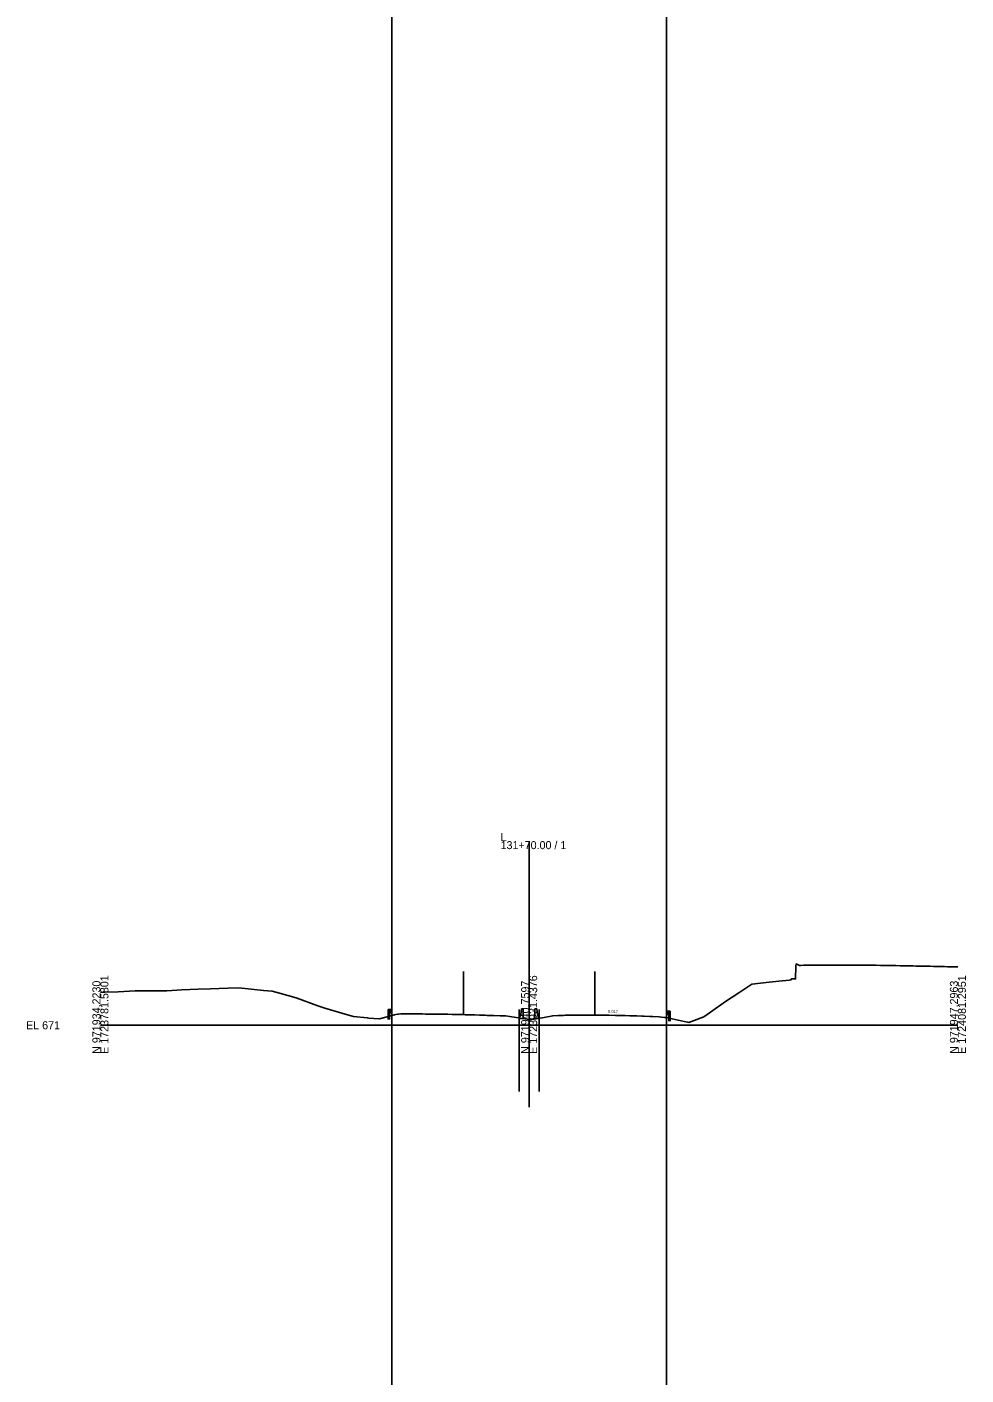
# Model space of a CAD drawing. Extents: x -26 to 303, y -29 to 15026.
# Drawn here: x -25.7 to 302.8, y 6377.7 to 6849.2 of the extents above; entities that cross this region are included whole.
import ezdxf

# ---------------------------------------------------------------- set-up
doc = ezdxf.new("R2010")
doc.units = 0
for name, color, linetype in [('Exist Cross Section Cell', 7, 'Continuous'), ('Exist XS Center Line Elevation Label', 7, 'Continuous'), ('Exist XS Ground Line', 7, 'Continuous'), ('Prop XS Ditch Standard Text', 7, 'Continuous'), ('Scratch_Level_0', 7, 'Continuous'), ('Typical Guardrail CELL', 7, 'Continuous'), ('Typical Median Barrier CELL', 7, 'Continuous')]:
    doc.layers.add(name, color=color, linetype=linetype)

msp = doc.modelspace()

# ---------------------------------------------------------------- linework, layer by layer
at = {"layer": 'Exist Cross Section Cell'}
for p, q in [((150, 6500), (150, 6564.41)), ((0, 6500), (150, 6500)), ((150, 6500), (300, 6500))]:
    msp.add_line(p, q, dxfattribs=at)
at = {"layer": 'Exist XS Ground Line'}
msp.add_lwpolyline([(0, 6511.5), (1.51, 6511.56), (6.17, 6511.73), (12.12, 6512.05), (18.24, 6512.02), (23.22, 6512.05), (28.46, 6512.36), (34.18, 6512.63), (38.47, 6512.75), (44.64, 6512.95), (48.48, 6513.12), (57.08, 6512.2), (60.09, 6511.97), (62.7, 6511.22), (68.49, 6509.6), (76.04, 6506.78), (78.5, 6505.99), (86.5, 6503.67), (88.51, 6503.12), (93.37, 6502.62), (93.94, 6502.48), (95.62, 6502.37), (97.68, 6502.21), (98.14, 6502.33), (102.9, 6503.63), (103.37, 6503.81), (103.91, 6503.88), (104.3, 6503.94), (105.15, 6503.98), (105.86, 6503.98), (107.61, 6503.99), (109.27, 6503.97), (110.13, 6503.97), (110.91, 6503.97), (111.29, 6503.97), (111.82, 6503.96), (112.64, 6503.95), (113.68, 6503.94), (115.14, 6503.92), (116.47, 6503.91), (117.64, 6503.9), (118.88, 6503.87), (120.13, 6503.85), (121.49, 6503.83), (123.06, 6503.81), (124.03, 6503.78), (125.11, 6503.76), (126.72, 6503.71), (127.62, 6503.69), (129.36, 6503.64), (130.14, 6503.62), (130.84, 6503.6), (132.62, 6503.56), (134.6, 6503.5), (135.32, 6503.47), (135.73, 6503.46), (137.2, 6503.42), (137.64, 6503.41), (139.81, 6503.35), (140.27, 6503.33), (141.77, 6503.29), (143.19, 6503.02), (150, 6502), (150.35, 6501.95), (155.21, 6502.72), (158.27, 6503.35), (160.13, 6503.4), (161.99, 6503.46), (162.65, 6503.49), (163.45, 6503.51), (164.44, 6503.53), (164.77, 6503.53), (165.16, 6503.53), (166.8, 6503.53), (167.67, 6503.53), (168.61, 6503.54), (170.2, 6503.55), (171.63, 6503.54), (172.69, 6503.53), (174.04, 6503.53), (175.2, 6503.53), (176.83, 6503.51), (177.25, 6503.51), (177.98, 6503.49), (180.18, 6503.44), (181.67, 6503.4), (182.67, 6503.38), (183.58, 6503.36), (185.18, 6503.31), (186.92, 6503.27), (187.67, 6503.25), (189.43, 6503.2), (190.2, 6503.16), (192.17, 6503.08), (192.67, 6503.06), (193.14, 6503.04), (195.5, 6502.91), (196.31, 6502.87), (197.33, 6502.74), (197.92, 6502.66), (199.05, 6502.53), (200.06, 6502.24), (204.21, 6501.36), (205.49, 6501.04), (205.84, 6501.02), (206.77, 6501.37), (211.14, 6502.97), (213.44, 6504.59), (218.63, 6508.35), (223.35, 6511.35), (227.88, 6514.34), (233.96, 6515.02), (238.54, 6515.57), (241.05, 6515.82), (241.65, 6515.95), (241.75, 6516.23), (242.3, 6516.23), (243.21, 6516.22), (243.31, 6520.72), (243.46, 6521.47), (244.58, 6520.93), (245.03, 6520.96), (245.94, 6520.99), (246.38, 6521), (246.98, 6521.01), (247.68, 6521.03), (250.01, 6521.05), (251.25, 6521.05), (252.63, 6521.04), (255.03, 6521.04), (257.75, 6521.05), (260.04, 6521.04), (260.45, 6521.04), (262.54, 6521.02), (264.48, 6521.02), (265.04, 6521.01), (266.88, 6521), (267.53, 6521), (268.24, 6520.99), (269.43, 6520.98), (271.37, 6520.97), (272.9, 6520.95), (273.95, 6520.93), (274.77, 6520.92), (276.6, 6520.89), (278.27, 6520.87), (279.75, 6520.83), (280.58, 6520.82), (282.34, 6520.78), (282.78, 6520.77), (284.33, 6520.74), (285.29, 6520.72), (286.33, 6520.7), (287.78, 6520.67), (288.94, 6520.65), (290.27, 6520.62), (291.51, 6520.59), (292.78, 6520.57), (293.91, 6520.54), (295.29, 6520.51), (296.32, 6520.48), (297.79, 6520.44), (298.73, 6520.42), (300, 6520.39)], dxfattribs=at)
at = {"layer": 'Scratch_Level_0'}
for p, q in [((102, 15009.56), (102, -28.7)), ((198, 15009.56), (198, -28.7)), ((127, 6518.8), (127, 6503.71)), ((173, 6518.8), (173, 6503.53)), ((146.46, 6505.5), (146.46, 6476.8)), ((153.54, 6505.5), (153.54, 6476.8)), ((173, 6503.53), (183.58, 6503.36)), ((150, 6500), (150, 6471.3)), ((150, 6500), (150, 6471.3))]:
    msp.add_line(p, q, dxfattribs=at)
at = {"layer": 'Typical Guardrail CELL'}
for p, q in [((101.18, 6505.51), (100.68, 6505.51)), ((100.68, 6505.51), (100.68, 6503.02)), ((101.18, 6503.02), (100.68, 6503.02)), ((100.68, 6503.02), (100.68, 6502.01)), ((101.18, 6505.51), (101.18, 6503.02)), ((101.18, 6505.51), (101.68, 6505.51)), ((101.18, 6504.35), (101.68, 6504.35)), ((101.18, 6503.02), (101.18, 6502.01)), ((101.68, 6505.51), (101.68, 6504.35)), ((101.68, 6505.51), (101.97, 6505.31)), ((101.68, 6504.98), (101.97, 6505.18)), ((101.68, 6504.93), (101.68, 6504.98)), ((101.68, 6504.93), (101.68, 6504.88)), ((101.68, 6504.88), (101.97, 6504.68)), ((101.68, 6504.35), (101.97, 6504.55)), ((198.32, 6504.94), (198.03, 6504.74)), ((198.32, 6504.41), (198.03, 6504.61)), ((198.32, 6504.31), (198.03, 6504.11)), ((198.32, 6503.78), (198.03, 6503.98)), ((198.82, 6504.94), (198.32, 6504.94)), ((198.32, 6504.94), (198.32, 6503.78)), ((198.32, 6504.36), (198.32, 6504.41)), ((198.32, 6504.36), (198.32, 6504.31)), ((198.82, 6503.78), (198.32, 6503.78)), ((198.82, 6504.94), (198.82, 6502.45)), ((198.82, 6504.94), (199.32, 6504.94)), ((199.32, 6504.94), (199.32, 6502.45)), ((198.82, 6502.45), (199.32, 6502.45)), ((198.82, 6502.45), (198.82, 6501.44)), ((199.32, 6502.45), (199.32, 6501.44))]:
    msp.add_line(p, q, dxfattribs=at)
for centre, start, end in [((101.92, 6505.24), 304.9888, 54.997), ((101.92, 6504.62), 304.9634, 54.9941), ((198.08, 6504.67), 125.003, 235.0112), ((198.08, 6504.05), 125.0059, 235.0366)]:
    msp.add_arc(centre, 0.0776, start, end, dxfattribs=at)
at = {"layer": 'Typical Median Barrier CELL'}
for p, q in [((146.46, 6502.75), (146.92, 6503.41)), ((146.46, 6502.34), (146.46, 6502.75)), ((147.07, 6503.8), (147.29, 6505.75)), ((147.29, 6505.75), (147.96, 6505.75)), ((147.96, 6505.75), (147.96, 6502.34)), ((152.71, 6505.75), (152.04, 6505.75)), ((152.04, 6505.75), (152.04, 6502.34)), ((152.93, 6503.8), (152.71, 6505.75)), ((153.54, 6502.75), (153.08, 6503.41)), ((153.54, 6502.34), (153.54, 6502.75)), ((147.96, 6502.34), (146.46, 6502.34)), ((152.04, 6502.34), (153.54, 6502.34))]:
    msp.add_line(p, q, dxfattribs=at)
for centre, start, end in [((146.24, 6503.89), 325.0039, 353.9447), ((153.76, 6503.89), 186.0553, 214.9961)]:
    msp.add_arc(centre, 0.833, start, end, dxfattribs=at)

# ---------------------------------------------------------------- texts
at = {"layer": 'Exist Cross Section Cell'}
for s, p in [('131+70.00 / 1', (140, 6561.61)), ('L', (140, 6564.41)), ('EL 671', (-26, 6498.6))]:
    msp.add_text(s, height=2.8, dxfattribs=at).set_placement(p)
for s, p in [('E 1723781.5801', (2.8, 6490)), ('E 1723931.4376', (152.8, 6490)), ('E 1724081.2951', (302.8, 6490)), ('N 971934.2230', (0, 6490)), ('N 971940.7597', (150, 6490)), ('N 971947.2963', (300, 6490))]:
    msp.add_text(s, height=2.8, rotation=90, dxfattribs=at).set_placement(p)
at = {"layer": 'Exist XS Center Line Elevation Label'}
msp.add_text('673.00', height=0.18, dxfattribs=at).set_placement((149.61, 6501.51))
at = {"layer": 'Prop XS Ditch Standard Text'}
msp.add_text('0.017', height=1, rotation=359.0407, dxfattribs=at).set_placement((177.6, 6504.31))

doc.saveas('drawing.dxf')
